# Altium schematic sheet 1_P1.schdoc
size 302 x 215 mm; Symbol: Sheet_A4; Device: Sheet_A4; @Project Name: Sheet_1; Company: YuzukiHD; Version: 1.0; @Page No: 1; @Page Count: 1; @Update Date: 2024-07-06 22:09:21; Comment: GloomyGhost
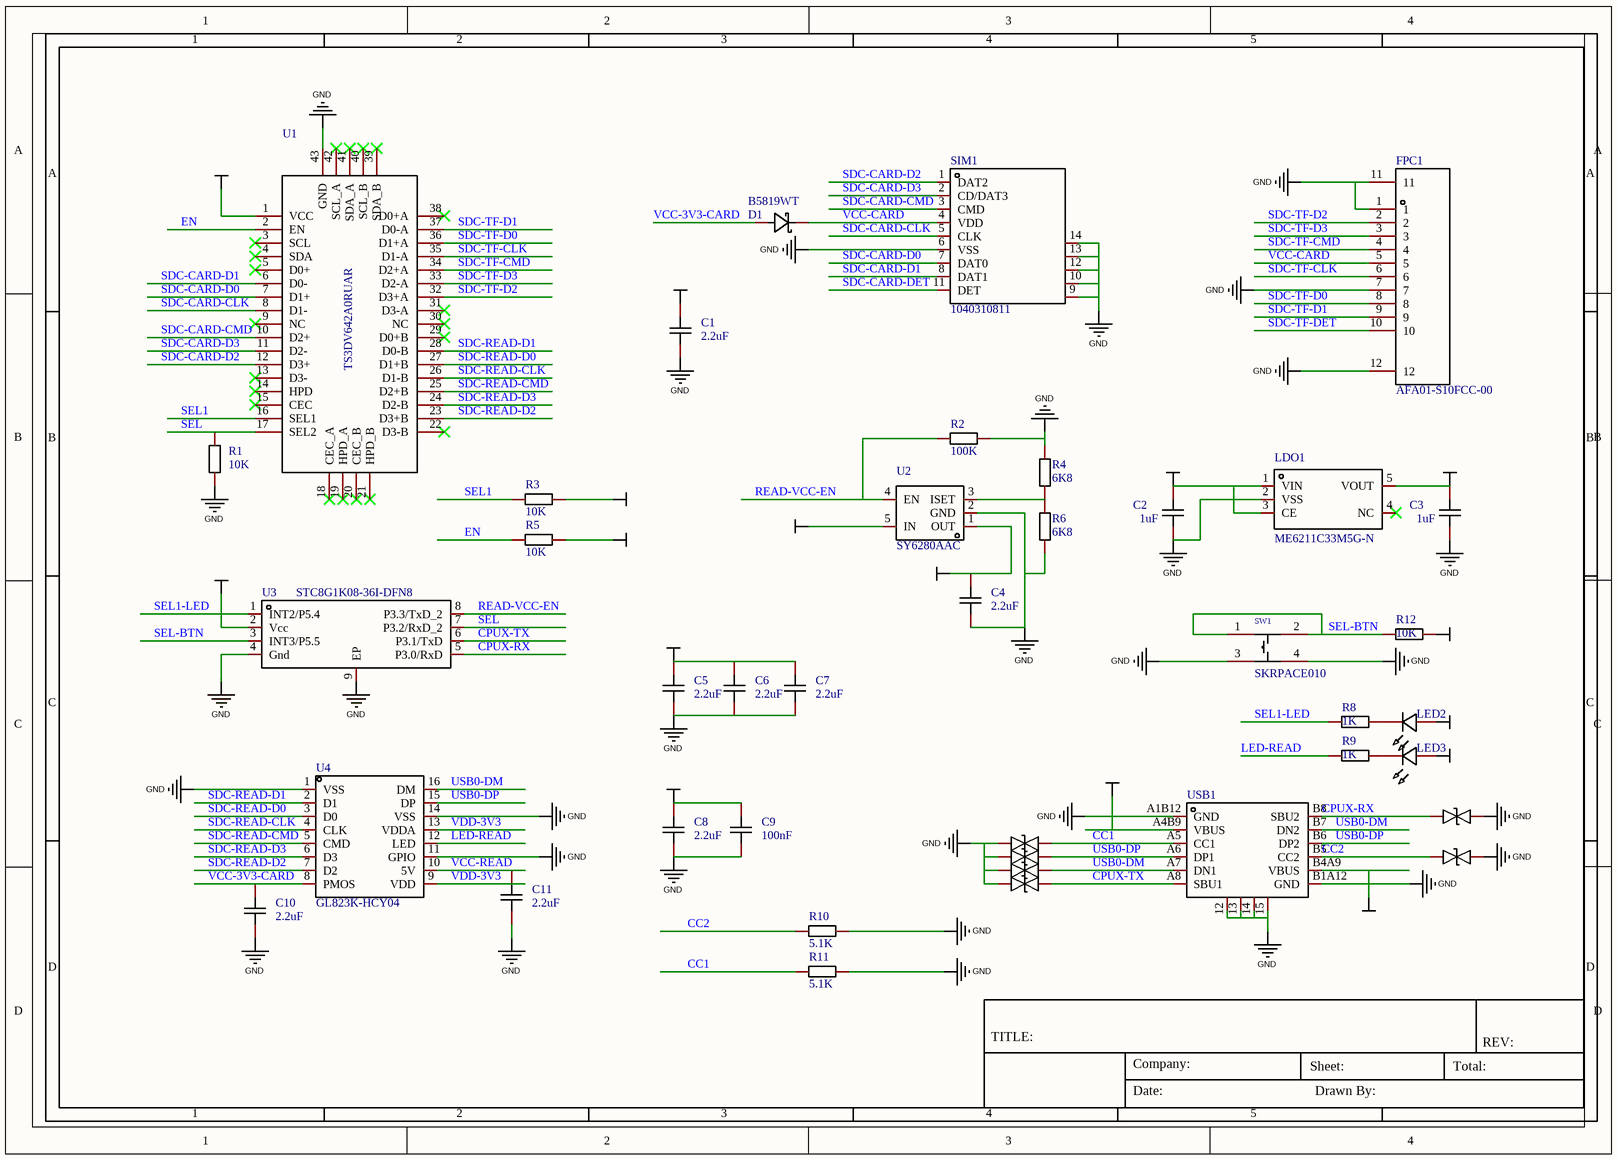
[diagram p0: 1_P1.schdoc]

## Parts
C1  2.2uF  [c0402-nsk]
C2  1uF  [C0603-NSK]
C3  1uF  [C0603-NSK]
C4  2.2uF  [c0402-nsk]
C5  2.2uF  [c0402-nsk]
C6  2.2uF  [c0402-nsk]
C7  2.2uF  [c0402-nsk]
C8  2.2uF  [c0402-nsk]
C9  100nF  [c0402-nsk]
C10  2.2uF  [c0402-nsk]
C11  2.2uF  [c0402-nsk]
D1  B5819WT  [SOD-523_L1.2-W0.8-LS1.6-RD-1 NSK]
D2  0402ESDA-05N  [d0402]  (value not drawn)
D3  0402ESDA-05N  [d0402]  (value not drawn)
D4  0402ESDA-05N  [d0402]  (value not drawn)
D5  0402ESDA-05N  [d0402]  (value not drawn)
D6  0402ESDA-05N  [d0402]  (value not drawn)
D7  0402ESDA-05N  [d0402]  (value not drawn)
FPC1  AFA01-S10FCC-00  [FPC-SMD_AFA01-S10FCC-00]
LDO1  ME6211C33M5G-N  [SOT-23-5_L3.0-W1.7-P0.95-LS2.8-BL]
LED2  LED_0603-R  [LED_0603]  (value not drawn)
LED3  LED_0603-R  [LED_0603]  (value not drawn)
R1  10K  [r0201 nsk]
R2  100K  [r0201 nsk]
R3  10K  [r0201 nsk]
R4  6K8  [r0201 nsk]
R5  10K  [r0201 nsk]
R6  6K8  [r0201 nsk]
R8  1K  [r0201 nsk]
R9  1K  [r0201 nsk]
R10  5.1K  [r0201 nsk]
R11  5.1K  [r0201 nsk]
R12  10K  [r0201 nsk]
SIM1  1040310811  [SIM-SMD_8P-1040310811]
SW1  SKRPACE010  [KEY-SMD_4P-L4.2-W3.2-P2.20-LS4.6]
U1  TS3DV642A0RUAR  [WFQFN-42_L9.0-W3.5-P0.50-BL-EP]
U2  SY6280AAC  [SOT-23-5_L3.0-W1.7-P0.95-LS2.8-BL]
U3  STC8G1K08-36I-DFN8  [DFN-8_L3.0-W3.0-P0.50-BL-EP]
U4  GL823K-HCY04  [SSOP-16_L4.9-W3.9-P0.64-LS6.0-BL]
USB1  TYPEC-304-BCP16  [USB-C-SMD_TYPEC-304-BCP16-1]  (value not drawn)

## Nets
GND: C1.1 C2.1 C3.1 C4.1 C5.1 C6.1 C7.1 C8.1 C9.1 C10.1 C11.1 D2.1 D3.1 D4.1 D5.1 D6.1 D7.1 FPC1.1 FPC1.7 FPC1.11 FPC1.12 LDO1.2(VSS) R1.2 R2.1 R4.2 R6.1 R10.1 R11.1 SIM1.6(VSS) SIM1.9 SIM1.10 SIM1.12 SIM1.13 SIM1.14 SW1.3 SW1.4 U1.43(GND) U2.2(GND) U3.4(Gnd) U3.9(EP) U4.1(VSS) U4.11(GPIO) U4.14(VSS) USB1.12 USB1.13 USB1.14 USB1.15 USB1.A1B12(GND) USB1.B1A12(GND)
VBUS-USB: C2.2 C5.2 C6.2 C7.2 LDO1.1(VIN) LDO1.3(CE) U2.5(IN) USB1.A4B9(VBUS) USB1.B4A9(VBUS)
VCC-3V3-LDO: C3.2 LDO1.5(VOUT) LED2.2(A) R3.2 R5.2 R12.1 U1.1(VCC) U3.2(Vcc)
VCC-CARD: C1.2 D1.1(K) FPC1.5 SIM1.4(VDD)
VCC-READ: C4.2 C11.2 U2.1(OUT) U4.10(5V)
VDD-3V3: C8.2 C9.2 LED3.2(A) U4.9(VDD) U4.13(VDDA)
CC1: D3.2 R11.2 USB1.A5(CC1)
CC2: D6.2 R10.2 USB1.B5(CC2)
CPUX-RX: D2.2 U3.5(P3.0/RxD) USB1.B8(SBU2)
CPUX-TX: D7.2 U3.6(P3.1/TxD) USB1.A8(SBU1)
EN: R5.1 U1.2(EN)
LED-READ: R9.2 U4.12(LED)
READ-VCC-EN: R2.2 U2.4(EN) U3.8(P3.3/TxD_2)
SDC-CARD-CLK: SIM1.5(CLK) U1.8(D1-)
SDC-CARD-CMD: SIM1.3(CMD) U1.10(D2+)
SDC-CARD-D0: SIM1.7(DAT0) U1.7(D1+)
SDC-CARD-D1: SIM1.8(DAT1) U1.6(D0-)
SDC-CARD-D2: SIM1.1(DAT2) U1.12(D3+)
SDC-CARD-D3: SIM1.2(CD/DAT3) U1.11(D2-)
SDC-CARD-DET: SIM1.11(DET)
SDC-READ-CLK: U1.26(D1-B) U4.4(CLK)
SDC-READ-CMD: U1.25(D2+B) U4.5(CMD)
SDC-READ-D0: U1.27(D1+B) U4.3(D0)
SDC-READ-D1: U1.28(D0-B) U4.2(D1)
SDC-READ-D2: U1.23(D3+B) U4.7(D2)
SDC-READ-D3: U1.24(D2-B) U4.6(D3)
SDC-TF-CLK: FPC1.6 U1.35(D1-A)
SDC-TF-CMD: FPC1.4 U1.34(D2+A)
SDC-TF-D0: FPC1.8 U1.36(D1+A)
SDC-TF-D1: FPC1.9 U1.37(D0-A)
SDC-TF-D2: FPC1.2 U1.32(D3+A)
SDC-TF-D3: FPC1.3 U1.33(D2-A)
SDC-TF-DET: FPC1.10
SEL: R1.1 U1.17(SEL2) U3.7(P3.2/RxD_2)
SEL1: R3.1 U1.16(SEL1)
SEL1-LED: R8.2 U3.1(INT2/P5.4)
SEL-BTN: R12.2 SW1.1 SW1.2 U3.3(INT3/P5.5)
USB0-DM: D5.2 U4.16(DM) USB1.A7(DN1) USB1.B7(DN2)
USB0-DP: D4.2 U4.15(DP) USB1.A6(DP1) USB1.B6(DP2)
VCC-3V3-CARD: C10.2 D1.2(A) U4.8(PMOS)
NetLED2_1: LED2.1(C) R8.1
NetLED3_1: LED3.1(C) R9.1
NetR4_1: R4.1 R6.2 U2.3(ISET)

Not connected (* = marked no-connect by the designer): LDO1 4(NC)*; U1 3(SCL)* 4(SDA)* 5(D0+)* 9(NC)* 13(D3-)* 14(HPD)* 15(CEC)* 18(CEC_A)* 19(HPD_A)* 20(CEC_B)* 21(HPD_B)* 22(D3-B)* 29(D0+B)* 30(NC)* 31(D3-A)* 38(D0+A)* 39(SDA_B)* 40(SCL_B)* 41(SDA_A)* 42(SCL_A)*

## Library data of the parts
C1 C4-C11 = CAP_0402: Symbol: CapAcitance; Convert to PCB: yes
C2 C3 = CAP_0603: Symbol: CapAcitance; Convert to PCB: yes
D1 = B5819WT_C2997265: 二极管配置:-;正向压降(Vf):600mV@200mA;直流反向耐压(Vr):40V;平均整流电流(Io):1A;; Manufacturer: BORN(伯恩半导体); Add into BOM: yes; Reverse Voltage (Vr): 40V; Average Rectified Current (Io): 1A; Reverse Leakage Current (Ir): 5uA@30V
D2-D7 = 0402ESDA-05N: 极性:Bidirectional;反向关断电压（典型值）:5V;击穿电压（最小值）:-;箝位电压:50V;峰值脉冲电流（10/1000us）:-;; Manufacturer: BORN伯恩半导体; Add into BOM: yes; Reverse Stand-Off Voltage (Vrwm): 5V; Clamping Voltage@Ipp: 50V
FPC1 = AFA01-S10FCC-00: 锁定特性:翻盖式;触点类型:下接;触点数量:10P;间距:1mm;安装类型:卧贴;; Manufacturer: JS(钜硕电子); Add into BOM: yes; Locking Feature: 翻盖式; Number of Contacts: 10P; Pitch: 1mm; FFC, FCB Thickness: 0.3mm
LDO1 = ME6211C33M5G-N: 输出类型:固定;最大输入电压:6V;输出电压:3.3V;最大输出电流:500mA;电源纹波抑制比(PSRR):70dB;输出极性:正极;; Manufacturer: MICRONE(南京微盟); Add into BOM: yes; Output Type: 固定; Maximum Input Voltage: 6V; Output Voltage: 3.3V; MAX Output Current: 500mA; Power Supply Rejection Ratio (PSRR): 70dB; Dropout Voltage: 260mV@(200mA); Output Polarity: 正极; Number of Outputs: 1
LED2 LED3 = LED_0603-R: Symbol: LED_R; Convert to PCB: yes
R1-R6 R8-R12 = Res_0201: Symbol: 电阻; Convert to PCB: yes
SIM1 = 1040310811: 卡连接方式:拔插式;卡类型:MicroSD卡(TF卡);连接器类型:卡座;本体最大高度:1.42mm;触头镀层:金;工作温度范围:-;; Manufacturer: MOLEX; Add into BOM: yes; Card Connection Mode: 拔插式; Connector Type: 卡座; Maximum Body Height: 1.42mm
SW1 = SKRPACE010: 电路结构:单刀单掷;按钮形状:椭圆形按钮;安装方式:立贴;开关长度:4.2mm;开关宽度:3.2mm;开关高度:2.5mm;触点电流:50mA;额定电压(DC):16V;带灯:-;机械寿命:-;; Manufacturer: ALPSALPINE(阿尔卑斯阿尔派); Add into BOM: yes; Circuit: 单刀单掷; Actuator Style: 椭圆形按钮; Switch Length: 4.2mm; Switch Width: 3.2mm; Switch Height: 2.5mm; Contact Current: 50mA; Voltage Rating (DC): 16V
U1 = TS3DV642A0RUAR: 开关电路:-;; Manufacturer: TI(德州仪器); Add into BOM: yes
U2 = SY6280AAC_C55136: 低能耗配电开关; Manufacturer: silergy(矽力杰); Add into BOM: yes
U3 = STC8G1K08-36I-DFN8: CPU内核:51系列;程序存储容量:8KB;RAM总容量:1.25KB;GPIO端口数量:6;工作电压范围:1.9V~5.5V;CPU最大主频:-;程序存储器类型:FLASH;; Manufacturer: STC(宏晶); Add into BOM: yes; CPU Core: 51系列; Program Storage Size: 8KB; RAM Size: 1.25KB; GPIO Ports Number: 6; Program Memory Type: FLASH; 16Bit Timer: 2; UART/USART: 1; Peripheral/Function: 低电压检测；看门狗；除法器；乘法器; Watchdog: 有
U4 = GL823K-HCY04: 应用功能:-;接口协议:-;; Manufacturer: GENESYS(创惟); Add into BOM: yes
USB1 = TYPEC-304-BCP16: Manufacturer: XUNPU; Pin Type: IN; Add into BOM: yes; Check: false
